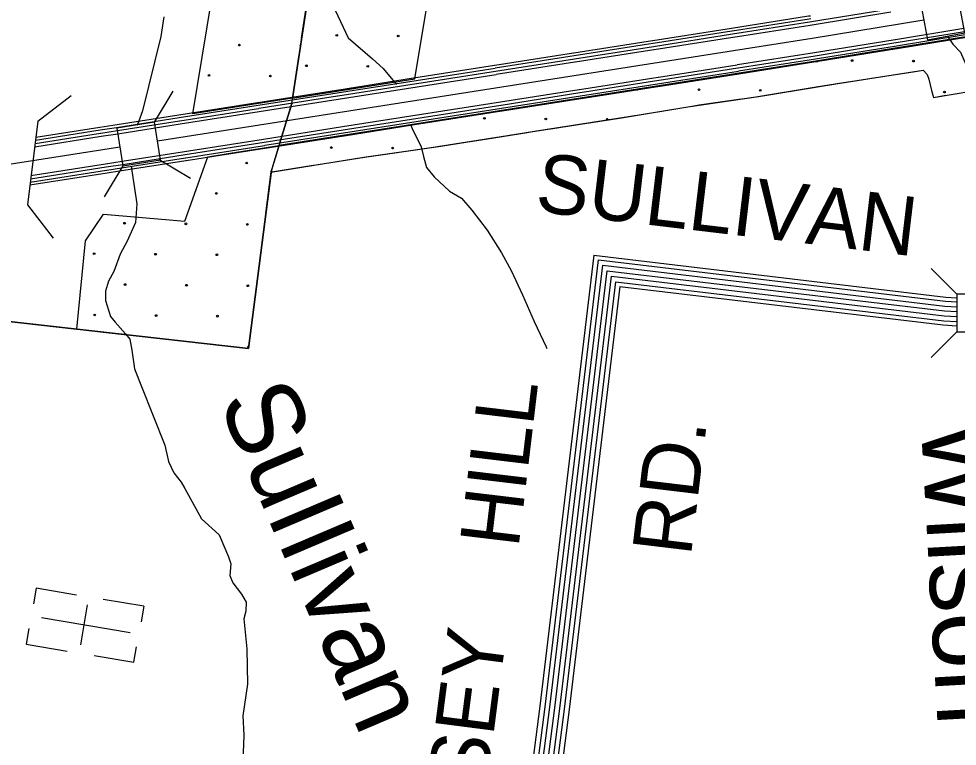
# Model space of a CAD drawing. Extents: x 1788175 to 1969470, y 584502 to 738744.
# Drawn here: x 1833978 to 1839858, y 668320 to 672880 of the extents above; entities that cross this region are included whole.
import ezdxf

# ---------------------------------------------------------------- set-up
doc = ezdxf.new("R2010")
doc.units = 0
for name, color, linetype in [('DESIGN - DRAINAGE - Bridges and Cross Drains Size Text', 7, 'Continuous'), ('DESIGN - EROSION CONTROL - Devices', 7, 'Continuous'), ('DESIGN - ROW - Right-of-Way and Easement Labels', 7, 'Continuous'), ('DESIGN - SCRATCH - User 1', 7, 'Continuous'), ('DESIGN - TRANSPORTATION - Text', 7, 'Continuous'), ('DESIGN - UTILITIES - Cable (Underground) with Text', 7, 'Continuous'), ('SURVEY - CENTERLINE - Preliminary', 7, 'Continuous'), ('SURVEY - DRAINAGE - Storm Sewer', 7, 'Continuous'), ('SURVEY - TRANSPORTATION - Roads', 7, 'Continuous'), ('SURVEY - VEGETATION - Features with Text', 7, 'Continuous')]:
    doc.layers.add(name, color=color, linetype=linetype)

msp = doc.modelspace()

# ---------------------------------------------------------------- linework, layer by layer
at = {"layer": 'DESIGN - EROSION CONTROL - Devices'}
for centre in [(1835970.4, 672775.5), (1836355, 672771.8), (1835360, 672714.5), (1839198.9, 672617.6), (1839583.5, 672613.9), (1835780, 672585.1), (1836164.6, 672581.4), (1835169.6, 672524.1), (1835554.2, 672520.4), (1838239.4, 672434.7), (1838623.9, 672430.9), (1839777.6, 672419.7), (1836895.3, 672255.4), (1837279.9, 672251.7), (1835935.8, 672072.5), (1836320.4, 672068.8), (1835405.7, 671975.1), (1835215.3, 671784.7), (1834640.3, 671598.1), (1835024.9, 671594.3), (1835409.4, 671590.6), (1834449.9, 671407.7), (1834834.5, 671403.9), (1835219, 671400.2), (1834644.1, 671213.5), (1835028.6, 671209.8), (1835413.2, 671206), (1834453.7, 671023.1), (1834838.2, 671019.4), (1835222.8, 671015.6)]:
    msp.add_circle(centre, 5.28, dxfattribs=at)
for centre, start, end in [((1835744.6, 672710.8), 95.84428, 246.97808), ((1837854.8, 672438.4), 190.17287, 7.66913), ((1835363.8, 672329.9), 16.63249, 181.20661), ((1837664.4, 672248), 356.38323, 201.32244), ((1835416.9, 670821.5), 59.23027, 286.21475)]:
    msp.add_arc(centre, 5.28, start, end, dxfattribs=at)
at = {"layer": 'DESIGN - SCRATCH - User 1'}
for points in [[(1835693.7, 672382.4), (1835067.6, 672284.2), (1835217.4, 673186.4), (1834869.2, 673248.1), (1834965.3, 673863.4), (1833840.9, 674016.5), (1833807.1, 674111.9), (1833766.8, 674160.7), (1833725.2, 674221.6), (1833717.2, 674248.7), (1833720, 674328.6), (1833706.7, 674479.6), (1833654.6, 674663.3), (1833575.9, 674818.8)], [(1835692.9, 672382.3), (1835971, 672426), (1836340.8, 672484), (1836459.9, 672502.7), (1836649.3, 673649.8), (1836455.9, 673686.9), (1836623.6, 674759.7)], [(1835827.3, 674521.6), (1835603, 673086.6), (1835794.5, 673049.9), (1835692.9, 672382.3)], [(1835827.3, 674521.6), (1835603, 673086.6), (1835794.5, 673049.9), (1835693.7, 672382.4)], [(1839973.1, 672776.7), (1839770.5, 672743.7), (1839520.1, 672702.9)], [(1839520.1, 672702.9), (1839237.3, 672656.8), (1838985.2, 672615.7), (1835607.9, 672085.6), (1835557.4, 671917.4)], [(1835557.4, 671917.4), (1836139.9, 672012), (1836622.9, 672080.3), (1837208.8, 672175.9), (1837864.2, 672277.9), (1838170.2, 672327.9), (1838612.9, 672393.1), (1839096.8, 672471.2), (1839643.7, 672558.1)], [(1839643.7, 672558.1), (1839669.1, 672529.5), (1839680, 672501.1), (1839696.7, 672430.4), (1839708.3, 672386.7), (1839955.1, 672428.1), (1840532.1, 672425.3), (1841166.1, 672430.1), (1841379.8, 672399), (1842066.2, 672308.9), (1842492.8, 672240.7)], [(1835607.9, 672085.6), (1835560.7, 671931.1), (1835418, 670813), (1833748.7, 671001.9)], [(1833748.7, 671001.9), (1834341.7, 670933.8), (1834395.1, 671488), (1834508.5, 671655), (1835018.4, 671610.4), (1835163.1, 672015.2), (1835301.6, 672037.5), (1835607.9, 672085.6)]]:
    msp.add_lwpolyline(points, dxfattribs=at)
at = {"layer": 'DESIGN - TRANSPORTATION - Text'}
for points in [[(1834895.2, 674501.5), (1834981.5, 674386.2), (1835120, 674274.4), (1835260.2, 674146.6), (1835418.5, 674022.5), (1835499.7, 673959.5), (1835539.1, 673915), (1835576.4, 673862.5), (1835615.4, 673785.9), (1835654.4, 673713.4), (1835703.3, 673628.7), (1835732.3, 673552.3), (1835751.1, 673458), (1835783.4, 673296.2), (1835816.3, 673221.3), (1835860.2, 673144.6), (1835911.3, 673067.9), (1835946, 672965.6), (1836042.1, 672759.8), (1836194.3, 672627.9), (1836261.5, 672567), (1836342.1, 672469.9), (1836344, 672466.9)], [(1834887, 672892), (1834867.4, 672768.1), (1834753.7, 672303.1), (1834728.9, 672233.3), (1834716.8, 672211.5)], [(1839800, 672770), (1839802.1, 672760.2), (1839830.9, 672720.2), (1839878.4, 672669.7), (1839914.1, 672589.5), (1839940.6, 672486.3), (1840091.2, 672228.2), (1840087.6, 672102.1), (1840103.4, 672001.2), (1840154.2, 671908.5), (1840154, 671879.4)], [(1836431.1, 672217), (1836442.6, 672192.5), (1836499.1, 672077.7), (1836514.3, 672015.4), (1836533.4, 671947.1), (1836580.6, 671888.5), (1836677.4, 671799.3), (1836750.8, 671754.3), (1836815.8, 671679.5), (1836912.1, 671554.2), (1837002.2, 671413), (1837062.8, 671302.2), (1837134.8, 671149.1), (1837206.6, 670982.1), (1837282.6, 670823.1), (1837286.2, 670813.9)], [(1834683.8, 671951.8), (1834685.1, 671925.6), (1834718.5, 671719), (1834709, 671603), (1834657.6, 671485.5), (1834612.7, 671404), (1834573.4, 671296.4), (1834540.6, 671234.7), (1834521.9, 671172.9), (1834521.1, 671114.8), (1834551.9, 671014.4), (1834581.4, 670978), (1834646.4, 670905.1), (1834673.9, 670870.8), (1834685.1, 670802.6), (1834703.6, 670686.2), (1834746.2, 670575.6), (1834893.4, 670207.5), (1834916.1, 670105.1), (1834949.2, 670034.7), (1834994.4, 669976.1), (1835017.9, 669935.8), (1835123.4, 669746.3), (1835234, 669644.9), (1835292.3, 669508), (1835305.7, 669463.8), (1835300.8, 669389.8), (1835318.2, 669343.6), (1835373.2, 669272.9), (1835402.6, 669222.5), (1835399.9, 669166.4), (1835387.3, 669118.5), (1835406.9, 668930.1), (1835410.2, 668709.9), (1835381.7, 668510.1), (1835388.2, 668389.9), (1835379.4, 668167.8)]]:
    msp.add_lwpolyline(points, dxfattribs=at)
at = {"layer": 'DESIGN - UTILITIES - Cable (Underground) with Text'}
for p, q in [((1834087, 669310.3), (1834070.5, 669211.9)), ((1834340.2, 669267.8), (1834087, 669310.2)), ((1834405.3, 669206.2), (1834363.5, 668956.1)), ((1834760.9, 669197.4), (1834506.3, 669240)), ((1834760.9, 669197.2), (1834744.4, 669099.1)), ((1834040.7, 669057.7), (1834024.4, 668960.1)), ((1834024.3, 668959.4), (1834281.6, 668916.4)), ((1834698.2, 668846.8), (1834714.4, 668943.7)), ((1834450.2, 668888.2), (1834698.2, 668846.7))]:
    msp.add_line(p, q, dxfattribs=at)
msp.add_lwpolyline([(1834120.7, 669126.8), (1834675.9, 669033.8)], dxfattribs=at)
at = {"layer": 'SURVEY - CENTERLINE - Preliminary'}
for points in [[(1839438, 672940.3), (1838944.5, 672859.8)], [(1839441.3, 672920.2), (1838947.8, 672839.8)], [(1834846.7, 672114.4), (1838948.7, 672758.1), (1839647.8, 672872.1)], [(1838937.6, 672896.7), (1838926.8, 672894.9), (1838444.4, 672819.2)], [(1838940.4, 672879.4), (1838929.6, 672877.7), (1838447.2, 672801.9)], [(1838943.7, 672859.7), (1838932.7, 672857.9), (1838450.3, 672782.2)], [(1838443.5, 672819.1), (1837949.6, 672741.6)], [(1838446.3, 672801.8), (1837952.3, 672724.3)], [(1838946.9, 672839.7), (1838935.9, 672837.9), (1838453.4, 672762.2)], [(1839899.4, 672818.2), (1839470.2, 672748.2)], [(1839903.1, 672798.2), (1839474.4, 672728.4)], [(1837948.7, 672741.4), (1837454.7, 672663.9)], [(1838449.4, 672782), (1837955.4, 672704.5)], [(1838452.5, 672762), (1837958.6, 672684.5)], [(1839469.3, 672748.1), (1838975.8, 672667.6)], [(1839473.5, 672728.2), (1838980, 672647.8)], [(1839919.1, 672780.6), (1839477.6, 672708.6)], [(1839939.9, 672766.2), (1839480.4, 672691.4)], [(1837951.4, 672724.1), (1837457.5, 672646.6)], [(1837954.5, 672704.4), (1837460.6, 672626.9)], [(1837957.7, 672684.3), (1837463.7, 672606.8)], [(1838974.9, 672667.5), (1838963.5, 672665.6), (1838480.4, 672589.8)], [(1839476.7, 672708.5), (1838983.2, 672628)], [(1839479.5, 672691.2), (1838986, 672610.8)], [(1837453.8, 672663.8), (1836959.9, 672586.2)], [(1837456.6, 672646.5), (1836962.6, 672568.9)], [(1837459.7, 672626.7), (1836965.7, 672549.2)], [(1837462.8, 672606.7), (1836968.9, 672529.2)], [(1838979.1, 672647.6), (1838966.7, 672645.6), (1838484.5, 672569.9)], [(1838982.3, 672627.9), (1838969.8, 672625.9), (1838487.6, 672550.2)], [(1838985.1, 672610.6), (1838972.6, 672608.6), (1838490.3, 672532.9)], [(1836959, 672586.1), (1836465, 672508.6)], [(1836961.7, 672568.8), (1836467.8, 672491.3)], [(1836964.8, 672549), (1836470.9, 672471.5)], [(1838479.5, 672589.7), (1837985.6, 672512.2)], [(1838483.6, 672569.8), (1837989.6, 672492.3)], [(1838486.7, 672550), (1837992.7, 672472.5)], [(1836464.1, 672508.4), (1835970.2, 672430.9)], [(1836466.9, 672491.1), (1835972.9, 672413.6)], [(1836968, 672529), (1836474, 672451.5)], [(1837984.7, 672512), (1837490.7, 672434.5)], [(1837988.7, 672492.1), (1837494.8, 672414.6)], [(1838489.4, 672532.7), (1837995.4, 672455.2)], [(1835969.3, 672430.8), (1835475.3, 672353.2)], [(1836470, 672471.4), (1835976, 672393.9)], [(1836473.1, 672451.3), (1835979.2, 672373.8)], [(1837489.8, 672434.4), (1836995.9, 672356.8)], [(1837991.8, 672472.4), (1837497.9, 672394.8)], [(1837994.5, 672455.1), (1837500.6, 672377.6)], [(1835972, 672413.5), (1835478.1, 672335.9)], [(1835975.1, 672393.7), (1835481.2, 672316.2)], [(1835978.3, 672373.7), (1835484.3, 672296.2)], [(1837493.9, 672414.5), (1836999.9, 672336.9)], [(1837497, 672394.7), (1837003, 672317.2)], [(1837499.7, 672377.4), (1837005.7, 672299.9)], [(1835474.5, 672353.1), (1834980.5, 672275.6)], [(1835477.2, 672335.8), (1834983.2, 672258.3)], [(1835480.3, 672316), (1834986.3, 672238.5)], [(1836995, 672356.7), (1836501, 672279.2)], [(1836999, 672336.8), (1836505.1, 672259.3)], [(1837002.1, 672317), (1836508.2, 672239.5)], [(1834979.6, 672275.4), (1834566.4, 672210.6)], [(1834982.3, 672258.1), (1834589.8, 672196.5)], [(1835483.4, 672296), (1834989.5, 672218.5)], [(1836500.1, 672279), (1836006.2, 672201.5)], [(1836504.2, 672259.1), (1836010.2, 672181.6)], [(1837004.8, 672299.7), (1836510.9, 672222.2)], [(1834484.8, 672197.8), (1834085.2, 672135.1)], [(1834566.4, 672210.6), (1834485.6, 672197.9)], [(1834589.8, 672196.5), (1834488.4, 672180.6)], [(1834985.4, 672238.4), (1834595.7, 672177.2)], [(1834988.6, 672218.4), (1834598.8, 672157.2)], [(1836005.3, 672201.4), (1835511.4, 672123.8)], [(1836507.3, 672239.4), (1836013.3, 672161.8)], [(1836510, 672222.1), (1836016.1, 672144.6)], [(1834493.7, 672140.7), (1834079.2, 672075.6)], [(1834490.6, 672160.7), (1834080.9, 672096.4)], [(1834487.5, 672180.5), (1834082.9, 672117)], [(1834595.7, 672177.2), (1834491.5, 672160.9)], [(1834598.8, 672157.2), (1834494.6, 672140.8)], [(1836009.3, 672181.5), (1835515.4, 672103.9)], [(1836012.4, 672161.7), (1835518.5, 672084.2)], [(1836015.2, 672144.4), (1835521.2, 672066.9)], [(1835510.5, 672123.7), (1835016.5, 672046.2)], [(1835514.5, 672103.8), (1835020.5, 672026.3)], [(1835517.6, 672084), (1835023.6, 672006.5)], [(1822966.8, 670273.6), (1827221.1, 670889.6), (1833367.6, 671882.2), (1834611.1, 672077.4)], [(1835015.6, 672046), (1834626, 671984.9)], [(1835019.6, 672026.1), (1834629.1, 671964.8)], [(1835520.3, 672066.7), (1835026.4, 671989.2)], [(1834520.8, 671968.4), (1834053.3, 671895)], [(1834626, 671984.9), (1834521.7, 671968.5)], [(1834629.1, 671964.8), (1834525.7, 671948.6)], [(1835025.5, 671989.1), (1834609, 671923.7)], [(1835022.7, 672006.4), (1834620.7, 671943.3)], [(1834530.6, 671911.4), (1834047.7, 671835.6)], [(1834527.9, 671928.7), (1834049.3, 671853.6)], [(1834524.8, 671948.5), (1834052, 671874.3)], [(1834620.7, 671943.3), (1834528.8, 671928.8)], [(1834609, 671923.7), (1834531.5, 671911.6)]]:
    msp.add_lwpolyline(points, dxfattribs=at)
at = {"layer": 'SURVEY - DRAINAGE - Storm Sewer'}
for p, q in [((1834827.8, 672230.5), (1834944.7, 672425.2)), ((1834858.3, 671997), (1835053, 671880.1)), ((1834630.1, 671958.8), (1834513.2, 671764.1)), ((1839854.2, 671154.3), (1839693.6, 671315)), ((1839854.2, 670916.7), (1839693.5, 670756.2))]:
    msp.add_line(p, q, dxfattribs=at)
for points in [[(1839670.8, 672747.4), (1839904.5, 672790.7), (1839861.2, 673024.3), (1839627.6, 672981)], [(1834630.1, 671958.8), (1834864.8, 671995.8), (1834827.8, 672230.5), (1834593.1, 672193.5)], [(1839854.2, 670916.7), (1840091.8, 670916.7), (1840091.8, 671154.3), (1839854.2, 671154.3)]]:
    msp.add_lwpolyline(points, close=True, dxfattribs=at)
for points in [[(1834098.2, 672237), (1834307, 672398.6)], [(1834098.2, 672237), (1834031.4, 671713.2)], [(1834031.4, 671713.2), (1834193, 671504.4)]]:
    msp.add_lwpolyline(points, dxfattribs=at)
at = {"layer": 'SURVEY - TRANSPORTATION - Roads'}
for points in [[(1837580.4, 671397.3), (1837242.9, 668572.2), (1837055, 667115), (1836917.4, 666180.5)], [(1837580.4, 671397.3), (1839785.7, 671134.4), (1839854.2, 671130.7)], [(1836949.4, 666175.8), (1837087, 667110.6), (1837274.9, 668568.2), (1837609.5, 671368.9)], [(1836980, 666171.3), (1837117.7, 667106.4), (1837305.7, 668564.4), (1837636.6, 671334.5)], [(1837609.5, 671368.9), (1839783.6, 671109.8), (1839854.2, 671105.9)], [(1837636.6, 671334.5), (1839780.9, 671078.9), (1839854.2, 671074.9)], [(1837010.7, 666166.8), (1837148.4, 667102.1), (1837336.5, 668560.5), (1837663.7, 671300)], [(1837010.7, 666166.8), (1837148.4, 667102.1), (1837336.5, 668560.5), (1837663.7, 671300)], [(1837041.4, 666162.3), (1837179.1, 667097.9), (1837367.2, 668556.7), (1837690.8, 671265.6)], [(1837663.7, 671300), (1839778.2, 671048), (1839854.2, 671043.8)], [(1837663.7, 671300), (1839778.2, 671048), (1839854.2, 671043.8)], [(1837690.8, 671265.6), (1839775.5, 671017.1), (1839854.2, 671012.8)], [(1837072, 666157.8), (1837209.8, 667093.7), (1837398, 668552.9), (1837717.9, 671231.1)], [(1837743.4, 671202.2), (1837426.5, 668549.4), (1837238.3, 667089.7), (1837100.4, 666153.6)], [(1837717.9, 671231.1), (1839772.8, 670986.2), (1839854.2, 670981.7)], [(1837743.4, 671202.2), (1839770.6, 670960.6), (1839854.2, 670956)]]:
    msp.add_lwpolyline(points, dxfattribs=at)
at = {"layer": 'SURVEY - VEGETATION - Features with Text'}
for points in [[(1835693.1, 672379.6), (1835794.5, 673049.9), (1835603, 673086.6), (1835827.3, 674521.6), (1834610.2, 674657.8), (1834723.7, 675460.7), (1835279.8, 675385.1), (1835347.3, 675884.1), (1835445, 676529.2), (1835501, 676898.3)], [(1835687.9, 672347.6), (1835794.5, 673049.9), (1835603, 673086.6), (1835827.3, 674521.6), (1834613.3, 674657.5)], [(1835755, 672789), (1835794.5, 673049.9), (1835794.4, 673049.9)], [(1835750, 672756.9), (1835789.6, 673017.9)], [(1835687.9, 672347.6), (1835727.5, 672608.6)], [(1835732.6, 672640.6), (1835693.1, 672379.6)], [(1835693.1, 672379.6), (1835732.6, 672640.6)], [(1835562.3, 671920.7), (1836144, 672013), (1836562.1, 672071.8), (1837187, 672170.8), (1837754.6, 672259.4), (1838194.2, 672332.7), (1838595.1, 672390), (1838973.1, 672452.2), (1839644.8, 672556.5)], [(1839581.8, 672546.7), (1839644.8, 672556.5)], [(1839643.8, 672556.6), (1839669.1, 672529.5), (1839680, 672501.1), (1839696.7, 672430.4), (1839708.3, 672386.7), (1839955.1, 672428.1), (1840532.1, 672425.3), (1841166.1, 672430.1), (1841379.8, 672399), (1842066.2, 672308.9), (1842492.8, 672240.7)], [(1839643.8, 672556.6), (1839669.1, 672529.5), (1839680, 672501.1), (1839696.7, 672430.4), (1839708.3, 672386.7), (1839785.9, 672399.7)], [(1839320.9, 672506.2), (1839581.8, 672546.7)], [(1838651.4, 672399.3), (1838911.9, 672442.2)], [(1838911.9, 672442.2), (1838973.1, 672452.2), (1839172.7, 672483.2)], [(1838241.7, 672339.5), (1838503.1, 672376.9)], [(1835687.9, 672347.6), (1835560.7, 671931.1)], [(1835610.8, 672095.1), (1835687.9, 672347.6)], [(1835687.9, 672347.6), (1835610.8, 672095.1)], [(1835687.9, 672347.6), (1835610.8, 672095.1)], [(1835687.9, 672347.6), (1835610.8, 672095.1)], [(1835687.9, 672347.6), (1835610.8, 672095.1)], [(1835610.8, 672095.1), (1835687.9, 672347.6)], [(1837981.1, 672297.2), (1838194.2, 672332.7), (1838241.7, 672339.5)], [(1837572.5, 672231), (1837754.6, 672259.4), (1837833.2, 672272.5)], [(1837311.6, 672190.3), (1837572.5, 672231)], [(1836902.7, 672125.8), (1837163.4, 672167.1)], [(1836641.9, 672084.4), (1836902.7, 672125.8)], [(1835971.2, 671985.6), (1836144, 672013), (1836232.2, 672025.4)], [(1836232.2, 672025.4), (1836493.6, 672062.2)], [(1835562.3, 671920.7), (1835823.1, 671962.1)], [(1833637.7, 671014.5), (1835418, 670813), (1835560.7, 671931.1)], [(1835526, 671658.8), (1835559.4, 671920.7)], [(1835559.4, 671920.7), (1835560.7, 671931.1)], [(1835567, 671951.7), (1835560.7, 671931.1)], [(1835567, 671951.7), (1835560.7, 671931.1)], [(1835567, 671951.7), (1835560.7, 671931.1)], [(1835567, 671951.7), (1835560.7, 671931.1)], [(1835567, 671951.7), (1835560.7, 671931.1)], [(1835473.5, 671248.1), (1835507, 671510)], [(1835440.1, 670986.3), (1835473.5, 671248.1)], [(1833832.7, 670992.4), (1834095.1, 670962.7)], [(1834244.1, 670945.8), (1834506.4, 670916.1)], [(1834506.4, 670916.1), (1834768.8, 670886.5)], [(1834917.8, 670869.6), (1835180.1, 670839.9)], [(1835180.1, 670839.9), (1835418, 670813), (1835421.1, 670837.5)]]:
    msp.add_lwpolyline(points, dxfattribs=at)

# ---------------------------------------------------------------- texts
at = {"layer": 'DESIGN - DRAINAGE - Bridges and Cross Drains Size Text'}
for s, rotation, p in [('SuIIivan', 293.05356, (1835224.8, 670483.2)), ('Wilson', 273.18096, (1839629.5, 670346))]:
    msp.add_text(s, height=475, rotation=rotation, dxfattribs=at).set_placement(p)
at = {"layer": 'DESIGN - ROW - Right-of-Way and Easement Labels'}
for s, rotation, p in [('SULLIVAN', 353.20321, (1837206, 671673.8)), ('HILL', 83.18815, (1837108.2, 669557)), ('RD.', 83.18823, (1838188.4, 669505.6)), ('S. POSEY', 82.65219, (1836739.3, 666741.3))]:
    msp.add_text(s, height=370, rotation=rotation, dxfattribs=at).set_placement(p)

doc.saveas('drawing.dxf')
